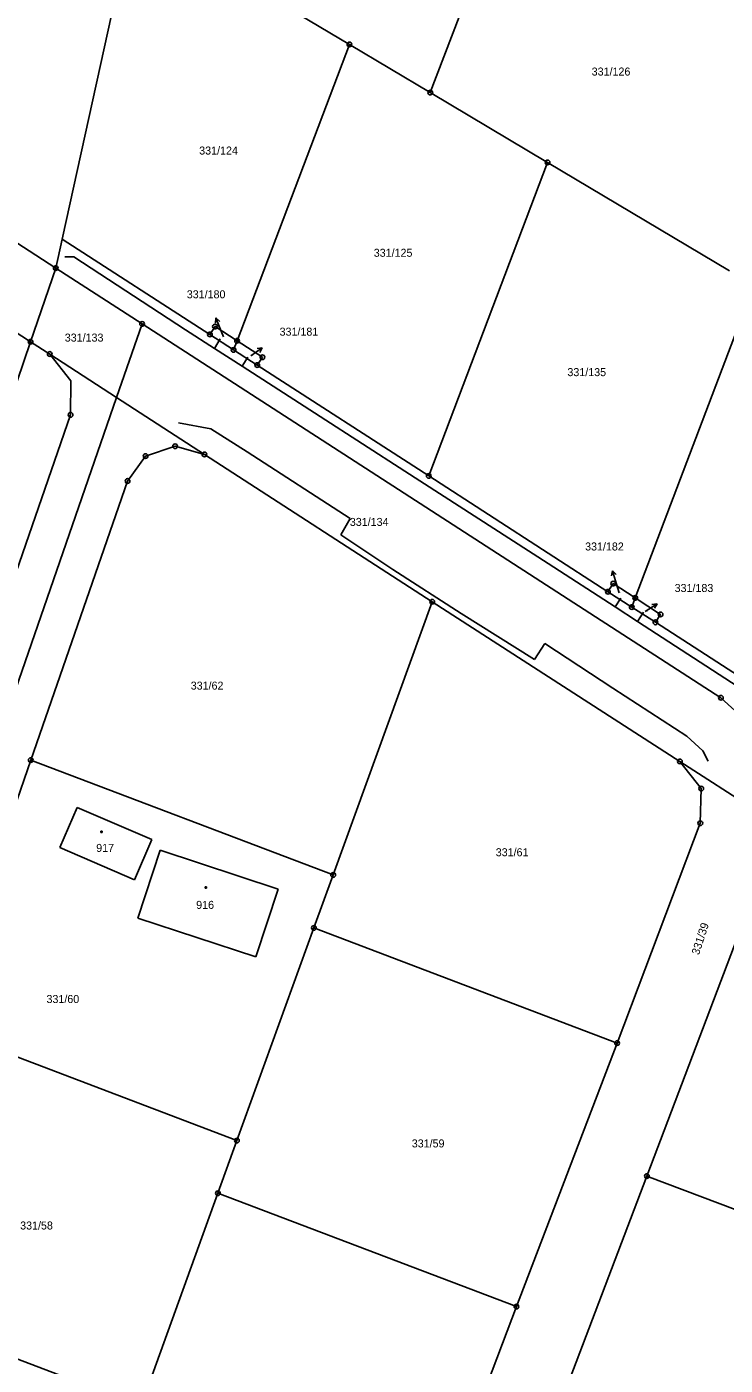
# Model space of a CAD drawing. Extents: x -770973 to -770265, y -1049936 to -1049427.
# Drawn here: x -770840.3 to -770766.1, y -1049695.4 to -1049553.2 of the extents above; entities that cross this region are included whole.
import ezdxf

# ---------------------------------------------------------------- set-up
doc = ezdxf.new("R2010")
doc.units = 0
for name, color, linetype in [('Vrstva 1', 7, 'Continuous'), ('Vrstva 13', 7, 'Continuous'), ('Vrstva 14', 7, 'Continuous'), ('Vrstva 15', 7, 'Continuous'), ('Vrstva 16', 7, 'Continuous'), ('Vrstva 25', 7, 'Continuous'), ('Vrstva 28', 7, 'Continuous'), ('Vrstva 50', 7, 'Continuous')]:
    doc.layers.add(name, color=color, linetype=linetype)

msp = doc.modelspace()

# ---------------------------------------------------------------- linework, layer by layer
at = {"layer": 'Vrstva 1'}
for p, q in [((-770789.36, -1049538.96), (-770797.43, -1049560.23)), ((-770828.98, -1049541.44), (-770836.54, -1049575.8)), ((-770806.02, -1049555.11), (-770828.98, -1049541.44)), ((-770806.02, -1049555.11), (-770817.96, -1049586.59)), ((-770797.43, -1049560.23), (-770806.02, -1049555.11)), ((-770865.61, -1049560.53), (-770837.22, -1049578.87)), ((-770797.43, -1049560.23), (-770784.97, -1049567.65)), ((-770868.21, -1049568.38), (-770839.89, -1049586.69)), ((-770784.97, -1049567.65), (-770797.6, -1049600.95)), ((-770784.97, -1049567.65), (-770765.65, -1049579.17)), ((-770836.54, -1049575.8), (-770837.22, -1049578.87)), ((-770820.84, -1049585.92), (-770836.54, -1049575.8)), ((-770837.22, -1049578.87), (-770839.89, -1049586.69)), ((-770837.22, -1049578.87), (-770828.04, -1049584.8)), ((-770763.07, -1049580.71), (-770775.67, -1049613.91)), ((-770830.75, -1049592.61), (-770828.04, -1049584.8)), ((-770766.56, -1049624.51), (-770828.04, -1049584.8)), ((-770820.84, -1049585.92), (-770820.3, -1049585.08)), ((-770820.3, -1049585.08), (-770817.96, -1049586.59)), ((-770839.89, -1049586.69), (-770849.2, -1049613.98)), ((-770839.89, -1049586.69), (-770837.86, -1049588)), ((-770818.33, -1049587.56), (-770820.84, -1049585.92)), ((-770817.96, -1049586.59), (-770818.33, -1049587.56)), ((-770817.96, -1049586.59), (-770815.27, -1049588.34)), ((-770837.86, -1049588), (-770830.75, -1049592.61)), ((-770837.86, -1049588), (-770835.62, -1049590.86)), ((-770815.81, -1049589.18), (-770818.33, -1049587.56)), ((-770815.27, -1049588.34), (-770815.81, -1049589.18)), ((-770797.6, -1049600.95), (-770815.81, -1049589.18)), ((-770835.62, -1049590.86), (-770835.64, -1049594.46)), ((-770895.53, -1049779.65), (-770830.75, -1049592.61)), ((-770830.75, -1049592.61), (-770821.42, -1049598.66)), ((-770835.64, -1049594.46), (-770843.13, -1049616.09)), ((-770824.54, -1049597.79), (-770827.67, -1049598.84)), ((-770821.42, -1049598.66), (-770824.54, -1049597.79)), ((-770827.67, -1049598.84), (-770829.59, -1049601.49)), ((-770797.23, -1049614.31), (-770821.42, -1049598.66)), ((-770778.56, -1049613.25), (-770797.6, -1049600.95)), ((-770839.87, -1049631.13), (-770829.59, -1049601.49)), ((-770778, -1049612.39), (-770778.56, -1049613.25)), ((-770775.67, -1049613.91), (-770778, -1049612.39)), ((-770778.56, -1049613.25), (-770776.03, -1049614.88)), ((-770775.67, -1049613.91), (-770776.03, -1049614.88)), ((-770772.97, -1049615.66), (-770775.67, -1049613.91)), ((-770807.75, -1049643.34), (-770797.23, -1049614.31)), ((-770770.92, -1049631.28), (-770797.23, -1049614.31)), ((-770776.03, -1049614.88), (-770773.52, -1049616.5)), ((-770773.52, -1049616.5), (-770772.97, -1049615.66)), ((-770754.04, -1049629.09), (-770773.52, -1049616.5)), ((-770763.19, -1049627.61), (-770766.56, -1049624.51)), ((-770839.87, -1049631.13), (-770849.67, -1049659.48)), ((-770839.87, -1049631.13), (-770807.75, -1049643.34)), ((-770770.92, -1049631.28), (-770760.32, -1049638.11)), ((-770768.65, -1049634.16), (-770770.92, -1049631.28)), ((-770768.75, -1049637.84), (-770768.65, -1049634.16)), ((-770834.95, -1049636.17), (-770836.79, -1049640.41)), ((-770827.01, -1049639.58), (-770834.95, -1049636.17)), ((-770777.59, -1049661.2), (-770768.75, -1049637.84)), ((-770774.43, -1049675.32), (-770760.32, -1049638.11)), ((-770828.84, -1049643.86), (-770827.01, -1049639.58)), ((-770836.79, -1049640.41), (-770828.84, -1049643.86)), ((-770826.12, -1049640.71), (-770828.5, -1049647.91)), ((-770813.59, -1049644.83), (-770826.12, -1049640.71)), ((-770809.79, -1049648.96), (-770807.75, -1049643.34)), ((-770815.96, -1049652.05), (-770813.59, -1049644.83)), ((-770828.5, -1049647.91), (-770815.96, -1049652.05)), ((-770817.97, -1049671.55), (-770809.79, -1049648.96)), ((-770809.79, -1049648.96), (-770777.59, -1049661.2)), ((-770817.97, -1049671.55), (-770849.67, -1049659.48)), ((-770777.59, -1049661.2), (-770788.28, -1049689.19)), ((-770820, -1049677.15), (-770817.97, -1049671.55)), ((-770774.43, -1049675.32), (-770786.51, -1049707.09)), ((-770740.34, -1049688.23), (-770774.43, -1049675.32)), ((-770828.17, -1049699.74), (-770820, -1049677.15)), ((-770788.28, -1049689.19), (-770820, -1049677.15)), ((-770859.49, -1049687.83), (-770828.17, -1049699.74)), ((-770798.96, -1049717.24), (-770788.28, -1049689.19))]:
    msp.add_line(p, q, dxfattribs=at)
at = {"layer": 'Vrstva 13'}
for p, q in [((-770819.4, -1049586.17), (-770819.65, -1049585.56)), ((-770777.37, -1049613.37), (-770777.64, -1049612.46))]:
    msp.add_line(p, q, dxfattribs=at)
at = {"layer": 'Vrstva 16'}
for p, q in [((-770820.21, -1049584.17), (-770820.25, -1049584.72)), ((-770819.65, -1049585.56), (-770820.21, -1049584.17)), ((-770820.21, -1049584.17), (-770819.79, -1049584.54)), ((-770816.51, -1049588.2), (-770815.28, -1049587.34)), ((-770815.28, -1049587.34), (-770815.84, -1049587.42)), ((-770815.28, -1049587.34), (-770815.55, -1049587.83)), ((-770778.08, -1049611.02), (-770778.17, -1049611.58)), ((-770777.64, -1049612.46), (-770778.08, -1049611.02)), ((-770778.08, -1049611.02), (-770777.69, -1049611.43)), ((-770774.6, -1049615.36), (-770773.35, -1049614.53)), ((-770773.35, -1049614.53), (-770773.91, -1049614.6)), ((-770773.35, -1049614.53), (-770773.63, -1049615.01))]:
    msp.add_line(p, q, dxfattribs=at)
at = {"layer": 'Vrstva 25'}
for p, q in [((-770832.42, -1049638.67), (-770832.27, -1049638.67)), ((-770832.42, -1049638.82), (-770832.42, -1049638.67)), ((-770832.27, -1049638.82), (-770832.42, -1049638.82)), ((-770832.27, -1049638.67), (-770832.27, -1049638.82)), ((-770821.35, -1049644.6), (-770821.2, -1049644.6)), ((-770821.35, -1049644.75), (-770821.35, -1049644.6)), ((-770821.2, -1049644.75), (-770821.35, -1049644.75)), ((-770821.2, -1049644.6), (-770821.2, -1049644.75))]:
    msp.add_line(p, q, dxfattribs=at)
at = {"layer": 'Vrstva 28'}
for centre, radius in [((-770806.02, -1049555.11), 0.25), ((-770806.02, -1049555.11), 0.005), ((-770797.43, -1049560.23), 0.25), ((-770797.43, -1049560.23), 0.005), ((-770784.97, -1049567.65), 0.25), ((-770784.97, -1049567.65), 0.005), ((-770837.22, -1049578.87), 0.25), ((-770837.22, -1049578.87), 0.005), ((-770828.04, -1049584.8), 0.25), ((-770828.04, -1049584.8), 0.005), ((-770820.3, -1049585.08), 0.25), ((-770820.3, -1049585.08), 0.005), ((-770839.89, -1049586.69), 0.25), ((-770839.89, -1049586.69), 0.005), ((-770820.84, -1049585.92), 0.25), ((-770820.84, -1049585.92), 0.005), ((-770817.96, -1049586.59), 0.25), ((-770817.96, -1049586.59), 0.005), ((-770837.86, -1049588), 0.25), ((-770837.86, -1049588), 0.005), ((-770818.33, -1049587.56), 0.25), ((-770818.33, -1049587.56), 0.005), ((-770815.27, -1049588.34), 0.25), ((-770815.27, -1049588.34), 0.005), ((-770815.81, -1049589.18), 0.25), ((-770815.81, -1049589.18), 0.005), ((-770835.64, -1049594.46), 0.25), ((-770835.64, -1049594.46), 0.005), ((-770824.54, -1049597.79), 0.25), ((-770824.54, -1049597.79), 0.005), ((-770827.67, -1049598.84), 0.25), ((-770827.67, -1049598.84), 0.005), ((-770821.42, -1049598.66), 0.25), ((-770821.42, -1049598.66), 0.005), ((-770797.6, -1049600.95), 0.25), ((-770797.6, -1049600.95), 0.005), ((-770829.59, -1049601.49), 0.25), ((-770829.59, -1049601.49), 0.005), ((-770778, -1049612.39), 0.25), ((-770778, -1049612.39), 0.005), ((-770778.56, -1049613.25), 0.25), ((-770778.56, -1049613.25), 0.005), ((-770775.67, -1049613.91), 0.25), ((-770775.67, -1049613.91), 0.005), ((-770797.23, -1049614.31), 0.25), ((-770797.23, -1049614.31), 0.005), ((-770776.03, -1049614.88), 0.25), ((-770776.03, -1049614.88), 0.005), ((-770772.97, -1049615.66), 0.25), ((-770773.52, -1049616.5), 0.25), ((-770773.52, -1049616.5), 0.005), ((-770772.97, -1049615.66), 0.005), ((-770766.56, -1049624.51), 0.25), ((-770766.56, -1049624.51), 0.005), ((-770839.87, -1049631.13), 0.25), ((-770770.92, -1049631.28), 0.25), ((-770839.87, -1049631.13), 0.005), ((-770770.92, -1049631.28), 0.005), ((-770768.65, -1049634.16), 0.25), ((-770768.65, -1049634.16), 0.005), ((-770768.75, -1049637.84), 0.25), ((-770768.75, -1049637.84), 0.005), ((-770807.75, -1049643.34), 0.25), ((-770807.75, -1049643.34), 0.005), ((-770809.79, -1049648.96), 0.25), ((-770809.79, -1049648.96), 0.005), ((-770777.59, -1049661.2), 0.25), ((-770777.59, -1049661.2), 0.005), ((-770817.97, -1049671.55), 0.25), ((-770817.97, -1049671.55), 0.005), ((-770774.43, -1049675.32), 0.25), ((-770774.43, -1049675.32), 0.005), ((-770820, -1049677.15), 0.25), ((-770820, -1049677.15), 0.005), ((-770788.28, -1049689.19), 0.25), ((-770788.28, -1049689.19), 0.005)]:
    msp.add_circle(centre, radius, dxfattribs=at)
at = {"layer": 'Vrstva 50'}
for p, q in [((-770835.3, -1049577.67), (-770836.26, -1049577.67)), ((-770823.44, -1049585.42), (-770835.3, -1049577.67)), ((-770820.34, -1049587.41), (-770823.44, -1049585.42)), ((-770820.34, -1049587.41), (-770819.74, -1049586.4)), ((-770817.4, -1049589.29), (-770820.34, -1049587.41)), ((-770817.4, -1049589.29), (-770816.83, -1049588.34)), ((-770809.13, -1049594.64), (-770817.4, -1049589.29)), ((-770824.17, -1049595.31), (-770820.73, -1049595.96)), ((-770800.15, -1049600.46), (-770809.13, -1049594.64)), ((-770820.73, -1049595.96), (-770816.9, -1049598.4)), ((-770816.9, -1049598.4), (-770805.95, -1049605.48)), ((-770784.92, -1049610.26), (-770800.15, -1049600.46)), ((-770805.95, -1049605.48), (-770806.95, -1049607.21)), ((-770806.95, -1049607.21), (-770801.41, -1049610.9)), ((-770801.41, -1049610.9), (-770794.16, -1049615.58)), ((-770777.8, -1049614.85), (-770784.92, -1049610.26)), ((-770777.8, -1049614.85), (-770777.2, -1049613.94)), ((-770775.41, -1049616.43), (-770777.8, -1049614.85)), ((-770775.41, -1049616.43), (-770774.77, -1049615.41)), ((-770794.16, -1049615.58), (-770786.35, -1049620.45)), ((-770764.12, -1049623.73), (-770775.41, -1049616.43)), ((-770786.35, -1049620.45), (-770785.27, -1049618.76)), ((-770785.27, -1049618.76), (-770778.04, -1049623.5)), ((-770778.04, -1049623.5), (-770770.17, -1049628.58)), ((-770770.17, -1049628.58), (-770768.47, -1049630.15)), ((-770768.47, -1049630.15), (-770767.93, -1049631.25))]:
    msp.add_line(p, q, dxfattribs=at)

# ---------------------------------------------------------------- texts
at = {"layer": 'Vrstva 14'}
for s, height, p in [('331/126', 0.85, (-770780.29, -1049558.42)), ('331/124', 0.85, (-770821.98, -1049566.81)), ('331/125', 0.85, (-770803.44, -1049577.67)), ('331/133', 0.85, (-770836.26, -1049586.68)), ('331/180', 0.05, (-770819.4, -1049586.17)), ('331/181', 0.05, (-770816.51, -1049588.2)), ('331/135', 0.85, (-770782.87, -1049590.35)), ('331/134', 0.85, (-770805.98, -1049606.26)), ('331/182', 0.05, (-770777.37, -1049613.37)), ('331/183', 0.05, (-770774.6, -1049615.36)), ('331/62', 0.85, (-770822.88, -1049623.65)), ('331/61', 0.85, (-770790.48, -1049641.35)), ('331/60', 0.85, (-770838.2, -1049656.94)), ('331/59', 0.85, (-770799.4, -1049672.28)), ('331/58', 0.85, (-770841, -1049681))]:
    msp.add_text(s, height=height, dxfattribs=at).set_placement(p)
msp.add_text('331/39', height=0.85, rotation=72, dxfattribs=at).set_placement((-770768.9, -1049651.89))
at = {"layer": 'Vrstva 15'}
for s, p in [('917', (-770832.92, -1049640.89)), ('916', (-770822.3, -1049646.94))]:
    msp.add_text(s, height=0.85, dxfattribs=at).set_placement(p)
at = {"layer": 'Vrstva 16'}
for s, p in [('331/180', (-770823.3, -1049582.08)), ('331/181', (-770813.44, -1049586.05)), ('331/182', (-770780.99, -1049608.87)), ('331/183', (-770771.48, -1049613.28))]:
    msp.add_text(s, height=0.85, dxfattribs=at).set_placement(p)

doc.saveas('drawing.dxf')
